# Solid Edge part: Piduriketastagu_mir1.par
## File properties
Author: Türk
Template: Iso Part.par
Last saved by: Türk
Revision: 2
Application: Solid Edge
Accuracy: 0,990
Username: Türk
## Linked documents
Piduriketastagu.par
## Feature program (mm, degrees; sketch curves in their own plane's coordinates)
part copy "CopiedPart_1"
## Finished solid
Body 1: solid body, 367 faces, 930 edges, 578 vertices.
  Faces by surface: plane 206, swept 68, cone 35, spline 34, cylinder 24
  Edges by curve: line 374, circle 250, spline 170, intersection 102, curve on surface 34
Bounding box of the edges (mm; curved faces can reach further): 260.000 x 30.000 x 260.000, from (-130, -15, -130) to (130, 15, 130).
Cylindrical faces by radius (mm): R6 x5, R62.1667 x17, R62.5 x1, R130 x1
Conical faces (half-angle, radius in mm at the cone's reference point): 18.4349 deg R57.5 x1, 45 deg R129 x17, 45 deg R130 x17
Planar faces by outward normal: +y 69, -y 52, oblique 85
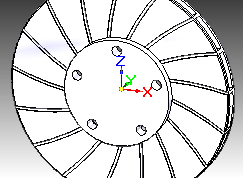
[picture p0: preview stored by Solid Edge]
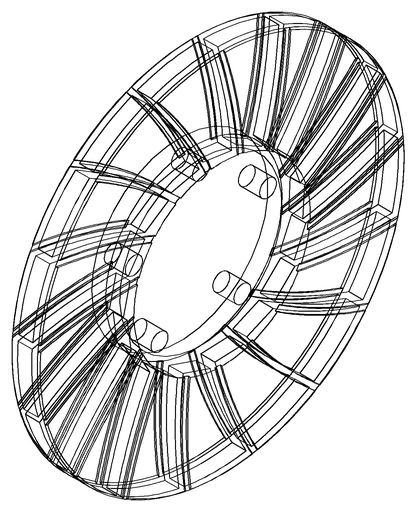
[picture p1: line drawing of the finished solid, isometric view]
